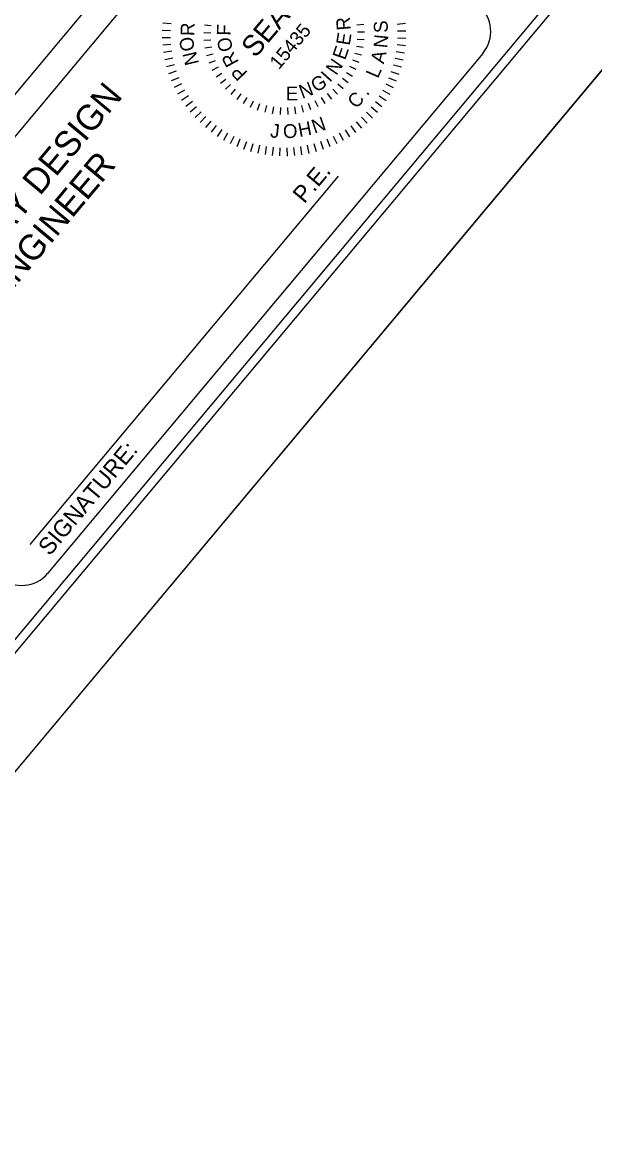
# Model space of a CAD drawing. Extents: x 555292 to 2368606, y 503623 to 1171444.
# Drawn here: x 2363221 to 2364064, y 1163175 to 1164815 of the extents above; entities that cross this region are included whole.
import ezdxf

# ---------------------------------------------------------------- set-up
doc = ezdxf.new("R2010")
doc.units = 0
for name, color, linetype in [('Old_Level_21', 7, 'Continuous'), ('Sheet Cutting Line CELL', 7, 'Continuous'), ('Sheet Plot Border Inside CELL', 7, 'Continuous'), ('Sheet Plot Border Outside CELL', 7, 'Continuous'), ('Sheet Title CELL', 7, 'Continuous')]:
    doc.layers.add(name, color=color, linetype=linetype)

msp = doc.modelspace()

# ---------------------------------------------------------------- linework, layer by layer
at = {"layer": 'Old_Level_21'}
for p, q in [((2363426.9, 1164803), (2363439.1, 1164802.6)), ((2363427.6, 1164813.8), (2363439.8, 1164812.7)), ((2363488, 1164799.5), (2363498.2, 1164799.3)), ((2363488.8, 1164810.9), (2363498.9, 1164809.7)), ((2363723.5, 1164811.6), (2363713.5, 1164810.3)), ((2363724.4, 1164800.2), (2363714.2, 1164799.9)), ((2363784.9, 1164812.7), (2363772.8, 1164811.6)), ((2363785.6, 1164801.8), (2363773.3, 1164801.5)), ((2363426.9, 1164792.1), (2363439.1, 1164792.5)), ((2363488.3, 1164788.1), (2363498.5, 1164788.9)), ((2363724.2, 1164788.8), (2363714, 1164789.5)), ((2363785.5, 1164791), (2363773.3, 1164791.4)), ((2363427.5, 1164781.3), (2363439.7, 1164782.4)), ((2363428.8, 1164770.6), (2363440.9, 1164772.4)), ((2363489.7, 1164776.8), (2363499.7, 1164778.5)), ((2363492.2, 1164765.6), (2363502, 1164768.3)), ((2363720.4, 1164766.3), (2363710.5, 1164768.9)), ((2363722.8, 1164777.4), (2363712.8, 1164779.1)), ((2363783.5, 1164769.4), (2363771.4, 1164771.3)), ((2363784.8, 1164780.2), (2363772.7, 1164781.3)), ((2363430.7, 1164759.9), (2363442.6, 1164762.4)), ((2363433.2, 1164749.4), (2363445, 1164752.6)), ((2363495.8, 1164754.8), (2363505.3, 1164758.4)), ((2363716.9, 1164755.4), (2363707.3, 1164759)), ((2363778.9, 1164748.3), (2363767.1, 1164751.6)), ((2363781.5, 1164758.8), (2363769.6, 1164761.4)), ((2363436.4, 1164739), (2363448, 1164742.9)), ((2363440.2, 1164728.9), (2363451.6, 1164733.5)), ((2363500.4, 1164744.3), (2363509.5, 1164748.8)), ((2363506, 1164734.3), (2363514.6, 1164739.7)), ((2363706.8, 1164734.9), (2363698.2, 1164740.2)), ((2363712.4, 1164744.9), (2363703.2, 1164749.4)), ((2363775.6, 1164737.9), (2363764.1, 1164741.9)), ((2363444.7, 1164719), (2363455.7, 1164724.3)), ((2363512.5, 1164724.9), (2363520.5, 1164731.1)), ((2363519.9, 1164716.2), (2363527.3, 1164723.2)), ((2363693, 1164716.7), (2363685.5, 1164723.6)), ((2363700.4, 1164725.5), (2363692.3, 1164731.6)), ((2363767.3, 1164717.9), (2363756.3, 1164723.3)), ((2363771.8, 1164727.8), (2363760.5, 1164732.5)), ((2363449.7, 1164709.3), (2363460.3, 1164715.3)), ((2363455.2, 1164700.1), (2363465.5, 1164706.7)), ((2363528.1, 1164708.3), (2363534.8, 1164715.9)), ((2363537, 1164701.1), (2363542.9, 1164709.4)), ((2363546.6, 1164694.9), (2363551.7, 1164703.7)), ((2363666.5, 1164695.2), (2363661.3, 1164704)), ((2363669.9, 1164709.7), (2363675.9, 1164701.5)), ((2363684.9, 1164708.7), (2363678.1, 1164716.3)), ((2363756.6, 1164699.1), (2363746.3, 1164705.8)), ((2363762.2, 1164708.4), (2363751.6, 1164714.4)), ((2363461.4, 1164691.1), (2363471.2, 1164698.3)), ((2363468, 1164682.6), (2363477.4, 1164690.4)), ((2363556.7, 1164689.6), (2363561, 1164698.9)), ((2363567.3, 1164685.3), (2363570.6, 1164695)), ((2363578.2, 1164682.1), (2363580.6, 1164692)), ((2363589.4, 1164679.9), (2363590.9, 1164690)), ((2363600.8, 1164678.9), (2363601.3, 1164689)), ((2363612.3, 1164678.9), (2363611.7, 1164689.1)), ((2363623.6, 1164680), (2363622.1, 1164690.1)), ((2363634.8, 1164682.3), (2363632.4, 1164692.1)), ((2363645.8, 1164685.6), (2363642.4, 1164695.2)), ((2363656.3, 1164689.9), (2363652, 1164699.1)), ((2363743.7, 1164681.7), (2363734.3, 1164689.5)), ((2363750.4, 1164690.2), (2363740.6, 1164697.5)), ((2363475.2, 1164674.4), (2363484.1, 1164682.8)), ((2363482.8, 1164666.8), (2363491.2, 1164675.6)), ((2363490.9, 1164659.5), (2363498.8, 1164668.9)), ((2363720.6, 1164658.8), (2363712.8, 1164668.2)), ((2363728.8, 1164666), (2363720.4, 1164674.9)), ((2363736.4, 1164673.6), (2363727.6, 1164682)), ((2363499.4, 1164652.8), (2363506.7, 1164662.6)), ((2363508.3, 1164646.6), (2363515, 1164656.9)), ((2363517.6, 1164641), (2363523.6, 1164651.6)), ((2363703.1, 1164646), (2363696.5, 1164656.3)), ((2363712.1, 1164652.1), (2363704.9, 1164662)), ((2363527.1, 1164635.9), (2363532.6, 1164646.9)), ((2363537, 1164631.4), (2363541.8, 1164642.7)), ((2363547.1, 1164627.6), (2363551.2, 1164639.1)), ((2363557.5, 1164624.3), (2363560.8, 1164636.1)), ((2363653.8, 1164624), (2363650.6, 1164635.8)), ((2363664.2, 1164627.2), (2363660.3, 1164638.8)), ((2363674.3, 1164631), (2363669.7, 1164642.3)), ((2363684.2, 1164635.4), (2363678.9, 1164646.4)), ((2363693.9, 1164640.4), (2363687.9, 1164651.1)), ((2363568, 1164621.7), (2363570.6, 1164633.6)), ((2363578.7, 1164619.7), (2363580.5, 1164631.8)), ((2363589.4, 1164618.4), (2363590.6, 1164630.5)), ((2363600.2, 1164617.7), (2363600.6, 1164629.9)), ((2363611.1, 1164617.6), (2363610.7, 1164629.9)), ((2363621.9, 1164618.3), (2363620.8, 1164630.4)), ((2363632.6, 1164619.5), (2363630.8, 1164631.6)), ((2363643.3, 1164621.5), (2363640.8, 1164633.4))]:
    msp.add_line(p, q, dxfattribs=at)
at = {"layer": 'Sheet Cutting Line CELL'}
msp.add_line((2359251.2, 1158978), (2364653.4, 1165436.5), dxfattribs=at)
at = {"layer": 'Sheet Plot Border Inside CELL'}
msp.add_lwpolyline([(2359232.5, 1159130.5), (2364578.6, 1165521.9), (2360532, 1168906.6), (2355185.9, 1162515.2)], close=True, dxfattribs=at)
at = {"layer": 'Sheet Plot Border Outside CELL'}
msp.add_line((2364704.7, 1165497.9), (2359251.2, 1158978), dxfattribs=at)
at = {"layer": 'Sheet Title CELL'}
for p, q in [((2362878.1, 1164249.5), (2363586, 1165095.8)), ((2362884, 1164318.8), (2363346.8, 1164872.1)), ((2363232.5, 1164045.3), (2363686.5, 1164587.9))]:
    msp.add_line(p, q, dxfattribs=at)
for points in [[(2359748.8, 1159767.7), (2364496.6, 1165443.8)], [(2363258.3, 1164002.5), (2363899.2, 1164768.7)]]:
    msp.add_lwpolyline(points, dxfattribs=at)
for centre, start, end in [((2363860.6, 1164801), 320.0895, 50.0895), ((2363219.8, 1164034.8), 230.0895, 320.0895)]:
    msp.add_arc(centre, 50, start, end, dxfattribs=at)

# ---------------------------------------------------------------- texts
at = {"layer": 'Old_Level_21'}
for s, height, rotation, p in [('SEAL', 30.57, 50.0097, (2363564, 1164760.9)), ('R', 20.4, 94.5746, (2363704.4, 1164803.6)), ('S', 20.4, 93.3341, (2363759.4, 1164799.6)), ('R', 20.4, 88.6702, (2363474.2, 1164794.3)), ('F', 20.4, 88.2503, (2363527.5, 1164794.8)), ('15435', 20.36, 50.0097, (2363598.6, 1164743.9)), ('E', 20.4, 80.8035, (2363702.8, 1164779.7)), ('O', 20.4, 101.727, (2363475.3, 1164774.1)), ('O', 20.4, 103.5465, (2363531.4, 1164773.9)), ('N', 20.4, 84.4515, (2363758, 1164776)), ('N', 20.4, 103.6864, (2363480.9, 1164754.1)), ('R', 20.4, 118.8428, (2363540.2, 1164756)), ('E', 20.4, 70.8176, (2363696.1, 1164758.1)), ('A', 20.4, 75.6289, (2363752.9, 1164752.6)), ('N', 20.4, 55.4255, (2363683, 1164735.4)), ('P', 20.4, 134.139, (2363553.7, 1164740.6)), ('G', 20.4, 29.7011, (2363653, 1164710.8)), ('I', 20.4, 47.7959, (2363673.6, 1164725.2)), ('L', 20.4, 66.6263, (2363744.4, 1164731)), ('E', 20.4, 0.0798, (2363608.9, 1164699.5)), ('N', 20.4, 20.9348, (2363632.9, 1164701.7)), ('C', 20.4, 46.0996, (2363712.2, 1164686.3)), ('.', 20.4, 53.842, (2363728.8, 1164705.4)), ('H', 20.4, 10.6593, (2363628.8, 1164645.5)), ('N', 20.4, 19.3318, (2363651, 1164650.5)), ('J', 20.4, 353.9447, (2363585.1, 1164645.3)), ('O', 20.4, 2.0165, (2363605, 1164643.8))]:
    msp.add_text(s, height=height, rotation=rotation, dxfattribs=at).set_placement(p)
at = {"layer": 'Sheet Title CELL'}
for s, height, p in [('ROADWAY DESIGN', 37.497, (2363071.5, 1164348.5)), ('ENGINEER', 37.5, (2363192.1, 1164403)), ('P.E.', 25, (2363636, 1164546.4)), ('SIGNATURE:', 25, (2363261.1, 1164027.2))]:
    msp.add_text(s, height=height, rotation=50.0895, dxfattribs=at).set_placement(p)

doc.saveas('drawing.dxf')
